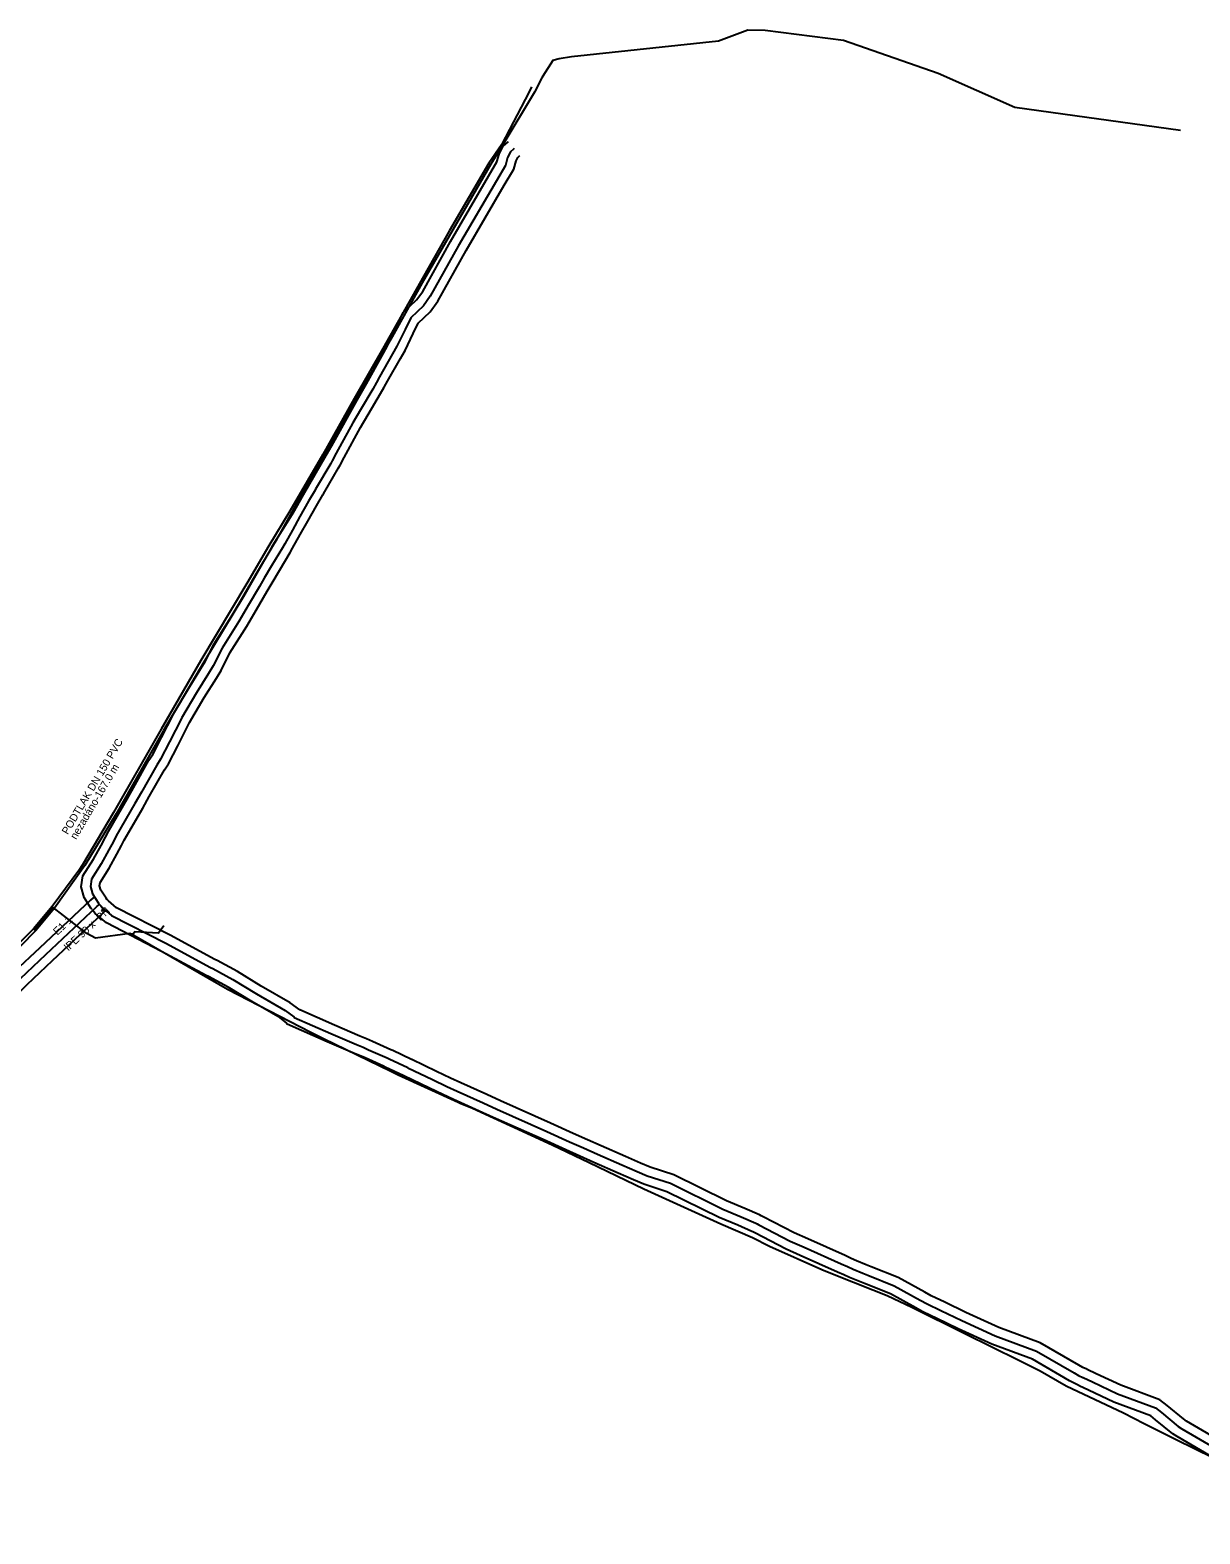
# Model space of a CAD drawing. Extents: x -599002 to -597744, y -1172604 to -1172149.
# Drawn here: x -598156 to -597956.6, y -1172520.9 to -1172264.5 of the extents above; entities that cross this region are included whole.
import ezdxf

# ---------------------------------------------------------------- set-up
doc = ezdxf.new("R2010")
doc.units = 0
for name, color, linetype in [('K Popis tlakové stoky', 7, 'Continuous'), ('K Přípojka', 7, 'Continuous'), ('K Stoka tlaková', 7, 'Continuous'), ('VP Řad', 7, 'Continuous'), ('VP Řad - ochranné pásmo tisk', 7, 'Continuous'), ('VP Řad - označení', 7, 'Continuous'), ('VP Řad - popis', 7, 'Continuous')]:
    doc.layers.add(name, color=color, linetype=linetype)

msp = doc.modelspace()

# ---------------------------------------------------------------- linework, layer by layer
at = {"layer": 'K Přípojka'}
msp.add_lwpolyline([(-598133.27, -1172417.21), (-598134.14, -1172418.43), (-598138.18, -1172418.23), (-598138.47, -1172418.6), (-598138.76, -1172418.64)], dxfattribs=at)
at = {"layer": 'K Stoka tlaková'}
for points in [[(-597959.98, -1172281.61), (-597988.21, -1172277.68), (-598001.24, -1172271.88), (-598017.41, -1172266.25), (-598030.74, -1172264.56), (-598033.69, -1172264.47), (-598038.7, -1172266.38), (-598063.77, -1172269.06), (-598065.85, -1172269.4), (-598066.93, -1172269.63), (-598068.65, -1172272.33), (-598068.82, -1172272.6), (-598070.08, -1172275.08), (-598075.46, -1172284.05), (-598077.49, -1172287.31), (-598089.21, -1172307.54), (-598094.33, -1172316.75), (-598094.95, -1172317.87), (-598095.53, -1172318.95), (-598095.87, -1172319.54), (-598098.78, -1172324.77), (-598100.35, -1172327.6), (-598104.69, -1172335.36), (-598105.61, -1172337), (-598109.5, -1172343.74), (-598111.28, -1172346.81), (-598114.54, -1172352.14), (-598114.89, -1172352.72), (-598119.69, -1172361.04), (-598126.44, -1172372.26), (-598133.3, -1172383.92), (-598141.39, -1172398.1), (-598146.73, -1172406.92), (-598151.91, -1172414.19), (-598155.09, -1172418), (-598168.17, -1172431.34)], [(-598070.56, -1172274.13), (-598070.97, -1172274.98), (-598075.71, -1172284.02), (-598077.85, -1172287.18), (-598084.54, -1172298.67), (-598088.96, -1172306.36), (-598095.91, -1172318.78), (-598100.81, -1172327.28), (-598106.13, -1172336.81), (-598111.78, -1172346.5), (-598115.36, -1172352.41), (-598119.09, -1172358.83), (-598126.92, -1172371.94), (-598133.69, -1172383.65), (-598141.83, -1172397.85), (-598147.11, -1172406.77), (-598147.76, -1172407.75), (-598152.3, -1172413.92), (-598155.49, -1172417.72)], [(-597944.95, -1172512.54), (-597960.69, -1172504.83), (-597966.15, -1172502.09), (-597969.66, -1172500.31), (-597979.45, -1172495.69), (-597983.86, -1172493.11), (-597987.52, -1172491.3), (-597996.7, -1172486.75), (-598005.73, -1172482.27), (-598009.97, -1172480.27), (-598012.38, -1172479.31), (-598018.99, -1172476.68), (-598021.12, -1172475.84), (-598030.03, -1172471.86), (-598032.92, -1172470.4), (-598038.32, -1172468.06), (-598051.44, -1172462.12), (-598060.77, -1172457.6), (-598067.04, -1172454.57), (-598080.65, -1172448.37), (-598082.75, -1172447.48), (-598083.09, -1172447.34), (-598093.28, -1172442.64), (-598094.55, -1172442.02), (-598106.02, -1172436.46), (-598108.17, -1172435.41), (-598122.39, -1172428.08), (-598138.76, -1172418.64), (-598139.02, -1172418.48), (-598144.87, -1172419.3), (-598146.38, -1172418.5), (-598146.81, -1172418.19), (-598152.11, -1172414.06), (-598155.29, -1172417.88), (-598155.49, -1172417.72)], [(-598155.49, -1172417.72), (-598168.6, -1172430.9), (-598174.15, -1172436.25), (-598184.78, -1172446.49), (-598199.75, -1172461.53), (-598212.93, -1172475.44), (-598229.88, -1172493.78), (-598241.35, -1172505.75), (-598246.4, -1172510.92), (-598245.59, -1172512.46), (-598245.34, -1172513.03)]]:
    msp.add_lwpolyline(points, dxfattribs=at)
at = {"layer": 'VP Řad'}
for points in [[(-598073.54, -1172284.67), (-598073.64, -1172284.75), (-598074.17, -1172285.21), (-598074.66, -1172286.18), (-598075.04, -1172287.56), (-598076.56, -1172290.16), (-598083.06, -1172301.3), (-598087.83, -1172309.85), (-598089.01, -1172311.47), (-598091.17, -1172313.53), (-598092.14, -1172315.54), (-598093.51, -1172318.38), (-598094.25, -1172319.68), (-598096.48, -1172323.6), (-598097.02, -1172324.57), (-598097.65, -1172325.67), (-598099.74, -1172329.24), (-598101.05, -1172331.46), (-598103.85, -1172336.61), (-598104.56, -1172337.93), (-598104.8, -1172338.36), (-598107.38, -1172342.76), (-598107.48, -1172342.92), (-598108.57, -1172344.79), (-598110.05, -1172347.43), (-598111.34, -1172349.72), (-598112.65, -1172352.07), (-598113.03, -1172352.74), (-598114.89, -1172355.84), (-598116.14, -1172357.93), (-598116.97, -1172359.36), (-598118.86, -1172362.6), (-598120.45, -1172365.32), (-598123.33, -1172369.87), (-598124.83, -1172372.89), (-598125.61, -1172374.15), (-598127.67, -1172377.49), (-598130.23, -1172381.78), (-598130.26, -1172381.83), (-598132.26, -1172385.8), (-598133.8, -1172388.8), (-598134.47, -1172389.78), (-598137.07, -1172394.41), (-598138.17, -1172396.36), (-598141.35, -1172401.87), (-598141.84, -1172402.8), (-598142.6, -1172404.26), (-598143.92, -1172406.6), (-598145.56, -1172409.24), (-598145.77, -1172410.47), (-598145.42, -1172411.74), (-598144.37, -1172413.33), (-598144.22, -1172413.57)], [(-598249.77, -1172520.25), (-598249.68, -1172519.68), (-598249.57, -1172519.45), (-598247.73, -1172518.69), (-598245.6, -1172517.83), (-598245.23, -1172517.67), (-598243.74, -1172516.54), (-598240.84, -1172513.19), (-598228.5, -1172499.37), (-598223.47, -1172493.84), (-598222.79, -1172493.1), (-598212.37, -1172481.65), (-598201.91, -1172470.38), (-598200.12, -1172468.46), (-598187.89, -1172455.3), (-598183.54, -1172451.25), (-598178.93, -1172447.33), (-598170.54, -1172438.78), (-598157.67, -1172426.17), (-598153.35, -1172422.06), (-598144.68, -1172413.93), (-598144.41, -1172413.67), (-598144.22, -1172413.57)], [(-598144.22, -1172413.57), (-598144.01, -1172413.78), (-598143.83, -1172414.02), (-598142.19, -1172415.41), (-598132.91, -1172420.18), (-598125.29, -1172424.28), (-598124.9, -1172424.49), (-598121.49, -1172426.32), (-598117.47, -1172428.79), (-598112.57, -1172431.61), (-598111.09, -1172432.71), (-598111.05, -1172432.8), (-598104.79, -1172435.56), (-598100.42, -1172437.41), (-598099.3, -1172437.89), (-598098.34, -1172438.32), (-598095.17, -1172439.73), (-598094.85, -1172439.87), (-598091.67, -1172441.38), (-598091.65, -1172441.39), (-598087.43, -1172443.42), (-598085.02, -1172444.58), (-598083.23, -1172445.39), (-598078.84, -1172447.38), (-598076.47, -1172448.46), (-598067.99, -1172452.24), (-598064.09, -1172454), (-598061.7, -1172455.07), (-598059.33, -1172456.14), (-598055.18, -1172457.94), (-598052.59, -1172459.07), (-598050.88, -1172459.81), (-598046.91, -1172461.09), (-598037.96, -1172465.51), (-598034.83, -1172466.84), (-598032.35, -1172467.89), (-598032.13, -1172468.01), (-598031.83, -1172468.16), (-598026.5, -1172470.95), (-598024.13, -1172472.01), (-598017.77, -1172474.84), (-598016.74, -1172475.3), (-598015.77, -1172475.73), (-598014.08, -1172476.41), (-598013.24, -1172476.75), (-598008.75, -1172478.56), (-598004.31, -1172481), (-598003.14, -1172481.64), (-598000.81, -1172482.76), (-597997.22, -1172484.5), (-597991.54, -1172487.09), (-597984.52, -1172489.69), (-597978.08, -1172493.42), (-597977.36, -1172493.84), (-597976.62, -1172494.2), (-597976.56, -1172494.23), (-597974.98, -1172494.97), (-597970.71, -1172496.97), (-597964.24, -1172499.37), (-597963.22, -1172500.2), (-597960.38, -1172502.54), (-597959.73, -1172502.95), (-597946.17, -1172510.88)]]:
    msp.add_lwpolyline(points, dxfattribs=at)
at = {"layer": 'VP Řad - ochranné pásmo tisk'}
for points in [[(-598145.53, -1172414.39), (-598145.67, -1172414.17), (-598146.84, -1172412.39), (-598147.35, -1172410.55), (-598147.03, -1172408.68), (-598145.25, -1172405.81), (-598143.96, -1172403.52), (-598143.21, -1172402.09), (-598142.7, -1172401.13), (-598139.51, -1172395.6), (-598138.42, -1172393.65), (-598135.78, -1172388.96), (-598135.13, -1172388.01), (-598133.64, -1172385.1), (-598131.63, -1172381.13), (-598131.58, -1172381.04), (-598128.99, -1172376.69), (-598126.92, -1172373.34), (-598126.18, -1172372.14), (-598124.68, -1172369.11), (-598121.77, -1172364.52), (-598120.2, -1172361.82), (-598118.31, -1172358.58), (-598117.47, -1172357.14), (-598116.21, -1172355.05), (-598114.37, -1172351.96), (-598114, -1172351.31), (-598112.68, -1172348.97), (-598111.4, -1172346.67), (-598109.91, -1172344.02), (-598108.81, -1172342.14), (-598108.71, -1172341.98), (-598106.15, -1172337.6), (-598105.92, -1172337.19), (-598105.2, -1172335.87), (-598102.4, -1172330.7), (-598101.08, -1172328.45), (-598098.99, -1172324.9), (-598098.37, -1172323.8), (-598097.82, -1172322.84), (-598095.59, -1172318.92), (-598094.88, -1172317.66), (-598093.53, -1172314.87), (-598092.44, -1172312.61), (-598090.18, -1172310.45), (-598089.13, -1172309.02), (-598084.4, -1172300.53), (-598077.89, -1172289.38), (-598076.48, -1172286.95), (-598076.11, -1172285.62), (-598075.41, -1172284.24), (-598074.63, -1172283.56), (-598074.5, -1172283.46)], [(-598142.91, -1172412.75), (-598143.07, -1172412.49), (-598144, -1172411.09), (-598144.19, -1172410.39), (-598144.09, -1172409.8), (-598142.59, -1172407.39), (-598141.24, -1172405), (-598140.47, -1172403.52), (-598140, -1172402.61), (-598136.83, -1172397.12), (-598135.73, -1172395.17), (-598133.16, -1172390.6), (-598132.47, -1172389.59), (-598130.88, -1172386.5), (-598128.88, -1172382.53), (-598128.88, -1172382.52), (-598126.35, -1172378.29), (-598124.3, -1172374.97), (-598123.48, -1172373.64), (-598121.98, -1172370.63), (-598119.13, -1172366.12), (-598117.53, -1172363.38), (-598115.64, -1172360.14), (-598114.81, -1172358.72), (-598113.56, -1172356.63), (-598111.69, -1172353.52), (-598111.31, -1172352.83), (-598109.99, -1172350.48), (-598108.7, -1172348.19), (-598107.23, -1172345.56), (-598106.14, -1172343.71), (-598106.05, -1172343.54), (-598103.45, -1172339.12), (-598103.21, -1172338.66), (-598102.49, -1172337.34), (-598099.7, -1172332.22), (-598098.41, -1172330.02), (-598096.31, -1172326.44), (-598095.68, -1172325.33), (-598095.13, -1172324.36), (-598092.91, -1172320.44), (-598092.14, -1172319.1), (-598090.75, -1172316.21), (-598089.9, -1172314.45), (-598087.84, -1172312.49), (-598086.53, -1172310.68), (-598081.72, -1172302.07), (-598075.23, -1172290.94), (-598073.6, -1172288.17), (-598073.21, -1172286.74), (-598072.93, -1172286.18), (-598072.65, -1172285.94), (-598072.58, -1172285.88)], [(-598144.94, -1172412.2), (-598145.32, -1172412.4), (-598145.74, -1172412.81), (-598154.41, -1172420.94), (-598158.74, -1172425.06), (-598171.63, -1172437.69), (-598179.98, -1172446.2), (-598184.57, -1172450.1), (-598188.98, -1172454.21), (-598201.25, -1172467.41), (-598203.04, -1172469.33), (-598213.51, -1172480.6), (-598223.93, -1172492.06), (-598224.61, -1172492.8), (-598229.65, -1172498.34), (-598242, -1172512.17), (-598244.8, -1172515.41), (-598246.01, -1172516.33), (-598246.2, -1172516.4), (-598248.31, -1172517.26), (-598250.71, -1172518.25), (-598251.17, -1172519.22), (-598251.3, -1172520.01)], [(-597945.41, -1172509.54), (-597958.93, -1172501.63), (-597959.47, -1172501.28), (-597962.24, -1172499.01), (-597963.46, -1172498.01), (-597970.11, -1172495.54), (-597974.32, -1172493.57), (-597975.89, -1172492.84), (-597975.95, -1172492.81), (-597976.63, -1172492.48), (-597977.31, -1172492.08), (-597983.86, -1172488.29), (-597990.95, -1172485.66), (-597996.56, -1172483.1), (-598000.14, -1172481.37), (-598002.43, -1172480.27), (-598003.56, -1172479.65), (-598008.09, -1172477.16), (-598012.67, -1172475.32), (-598013.51, -1172474.98), (-598015.17, -1172474.31), (-598016.11, -1172473.89), (-598017.14, -1172473.43), (-598023.5, -1172470.59), (-598025.83, -1172469.56), (-598031.11, -1172466.79), (-598031.41, -1172466.64), (-598031.69, -1172466.49), (-598034.23, -1172465.42), (-598037.32, -1172464.11), (-598046.33, -1172459.65), (-598050.33, -1172458.36), (-598051.98, -1172457.65), (-598054.56, -1172456.53), (-598058.71, -1172454.73), (-598061.06, -1172453.66), (-598063.45, -1172452.59), (-598067.36, -1172450.83), (-598075.84, -1172447.05), (-598078.2, -1172445.98), (-598082.6, -1172443.98), (-598084.37, -1172443.18), (-598086.76, -1172442.03), (-598090.98, -1172440), (-598091.01, -1172439.99), (-598094.2, -1172438.47), (-598094.54, -1172438.32), (-598097.71, -1172436.91), (-598098.68, -1172436.47), (-598099.82, -1172435.99), (-598104.18, -1172434.14), (-598110.07, -1172431.54), (-598111.72, -1172430.32), (-598116.68, -1172427.46), (-598120.72, -1172424.98), (-598124.17, -1172423.13), (-598124.56, -1172422.92), (-598132.19, -1172418.81), (-598141.33, -1172414.12), (-598142.7, -1172412.95), (-598142.84, -1172412.77), (-598143.13, -1172412.48)], [(-598143.87, -1172414.23), (-598143.34, -1172414.78), (-598143.62, -1172415.05), (-598152.29, -1172423.18), (-598156.6, -1172427.28), (-598169.45, -1172439.87), (-598177.88, -1172448.46), (-598182.51, -1172452.4), (-598186.8, -1172456.39), (-598198.99, -1172469.51), (-598200.77, -1172471.43), (-598211.23, -1172482.7), (-598221.65, -1172494.14), (-598222.32, -1172494.88), (-598227.35, -1172500.4), (-598239.68, -1172514.21), (-598242.68, -1172517.67), (-598244.45, -1172519.01), (-598245, -1172519.26), (-598247.15, -1172520.12), (-598248.98, -1172520.88), (-598249.2, -1172520.34)], [(-597946.93, -1172512.22), (-597960.53, -1172504.27), (-597961.29, -1172503.8), (-597964.21, -1172501.4), (-597965.02, -1172500.73), (-597971.31, -1172498.4), (-597975.63, -1172496.37), (-597977.23, -1172495.62), (-597977.3, -1172495.59), (-597978.09, -1172495.2), (-597978.86, -1172494.76), (-597985.18, -1172491.09), (-597992.13, -1172488.52), (-597997.88, -1172485.9), (-598001.48, -1172484.16), (-598003.85, -1172483.01), (-598005.05, -1172482.35), (-598009.41, -1172479.96), (-598013.82, -1172478.18), (-598014.66, -1172477.84), (-598016.37, -1172477.15), (-598017.37, -1172476.71), (-598018.4, -1172476.25), (-598024.76, -1172473.42), (-598027.17, -1172472.34), (-598032.54, -1172469.53), (-598032.85, -1172469.37), (-598033.01, -1172469.29), (-598035.43, -1172468.26), (-598038.6, -1172466.91), (-598047.49, -1172462.53), (-598051.43, -1172461.26), (-598053.21, -1172460.48), (-598055.79, -1172459.36), (-598059.95, -1172457.55), (-598062.33, -1172456.48), (-598064.72, -1172455.41), (-598068.62, -1172453.65), (-598077.1, -1172449.87), (-598079.48, -1172448.79), (-598083.87, -1172446.8), (-598085.67, -1172445.98), (-598088.1, -1172444.81), (-598092.32, -1172442.78), (-598092.33, -1172442.78), (-598095.5, -1172441.27), (-598095.8, -1172441.14), (-598098.96, -1172439.73), (-598099.92, -1172439.31), (-598101.03, -1172438.84), (-598105.4, -1172436.98), (-598112.22, -1172433.97), (-598112.34, -1172433.71), (-598113.42, -1172432.9), (-598118.26, -1172430.12), (-598122.26, -1172427.66), (-598125.63, -1172425.85), (-598126.02, -1172425.64), (-598133.63, -1172421.55), (-598143.05, -1172416.7), (-598144.96, -1172415.09), (-598145.18, -1172414.79), (-598145.31, -1172414.66)]]:
    msp.add_lwpolyline(points, dxfattribs=at)

# ---------------------------------------------------------------- texts
at = {"layer": 'K Popis tlakové stoky'}
for s, p in [('PODTLAK DN 150 PVC', (-598149.62, -1172401.74)), ('nezadáno-167.0 m', (-598148.2, -1172402.58))]:
    msp.add_text(s, height=1.3, rotation=59.3823, dxfattribs=at).set_placement(p)
at = {"layer": 'VP Řad - označení'}
msp.add_text('E1-1', height=1.3, rotation=43.159, dxfattribs=at).set_placement((-598151.39, -1172418.88))
at = {"layer": 'VP Řad - popis'}
msp.add_text('lPE 90 x  PN ', height=1.3, rotation=43.159, dxfattribs=at).set_placement((-598149.5, -1172421.55))

doc.saveas('drawing.dxf')
